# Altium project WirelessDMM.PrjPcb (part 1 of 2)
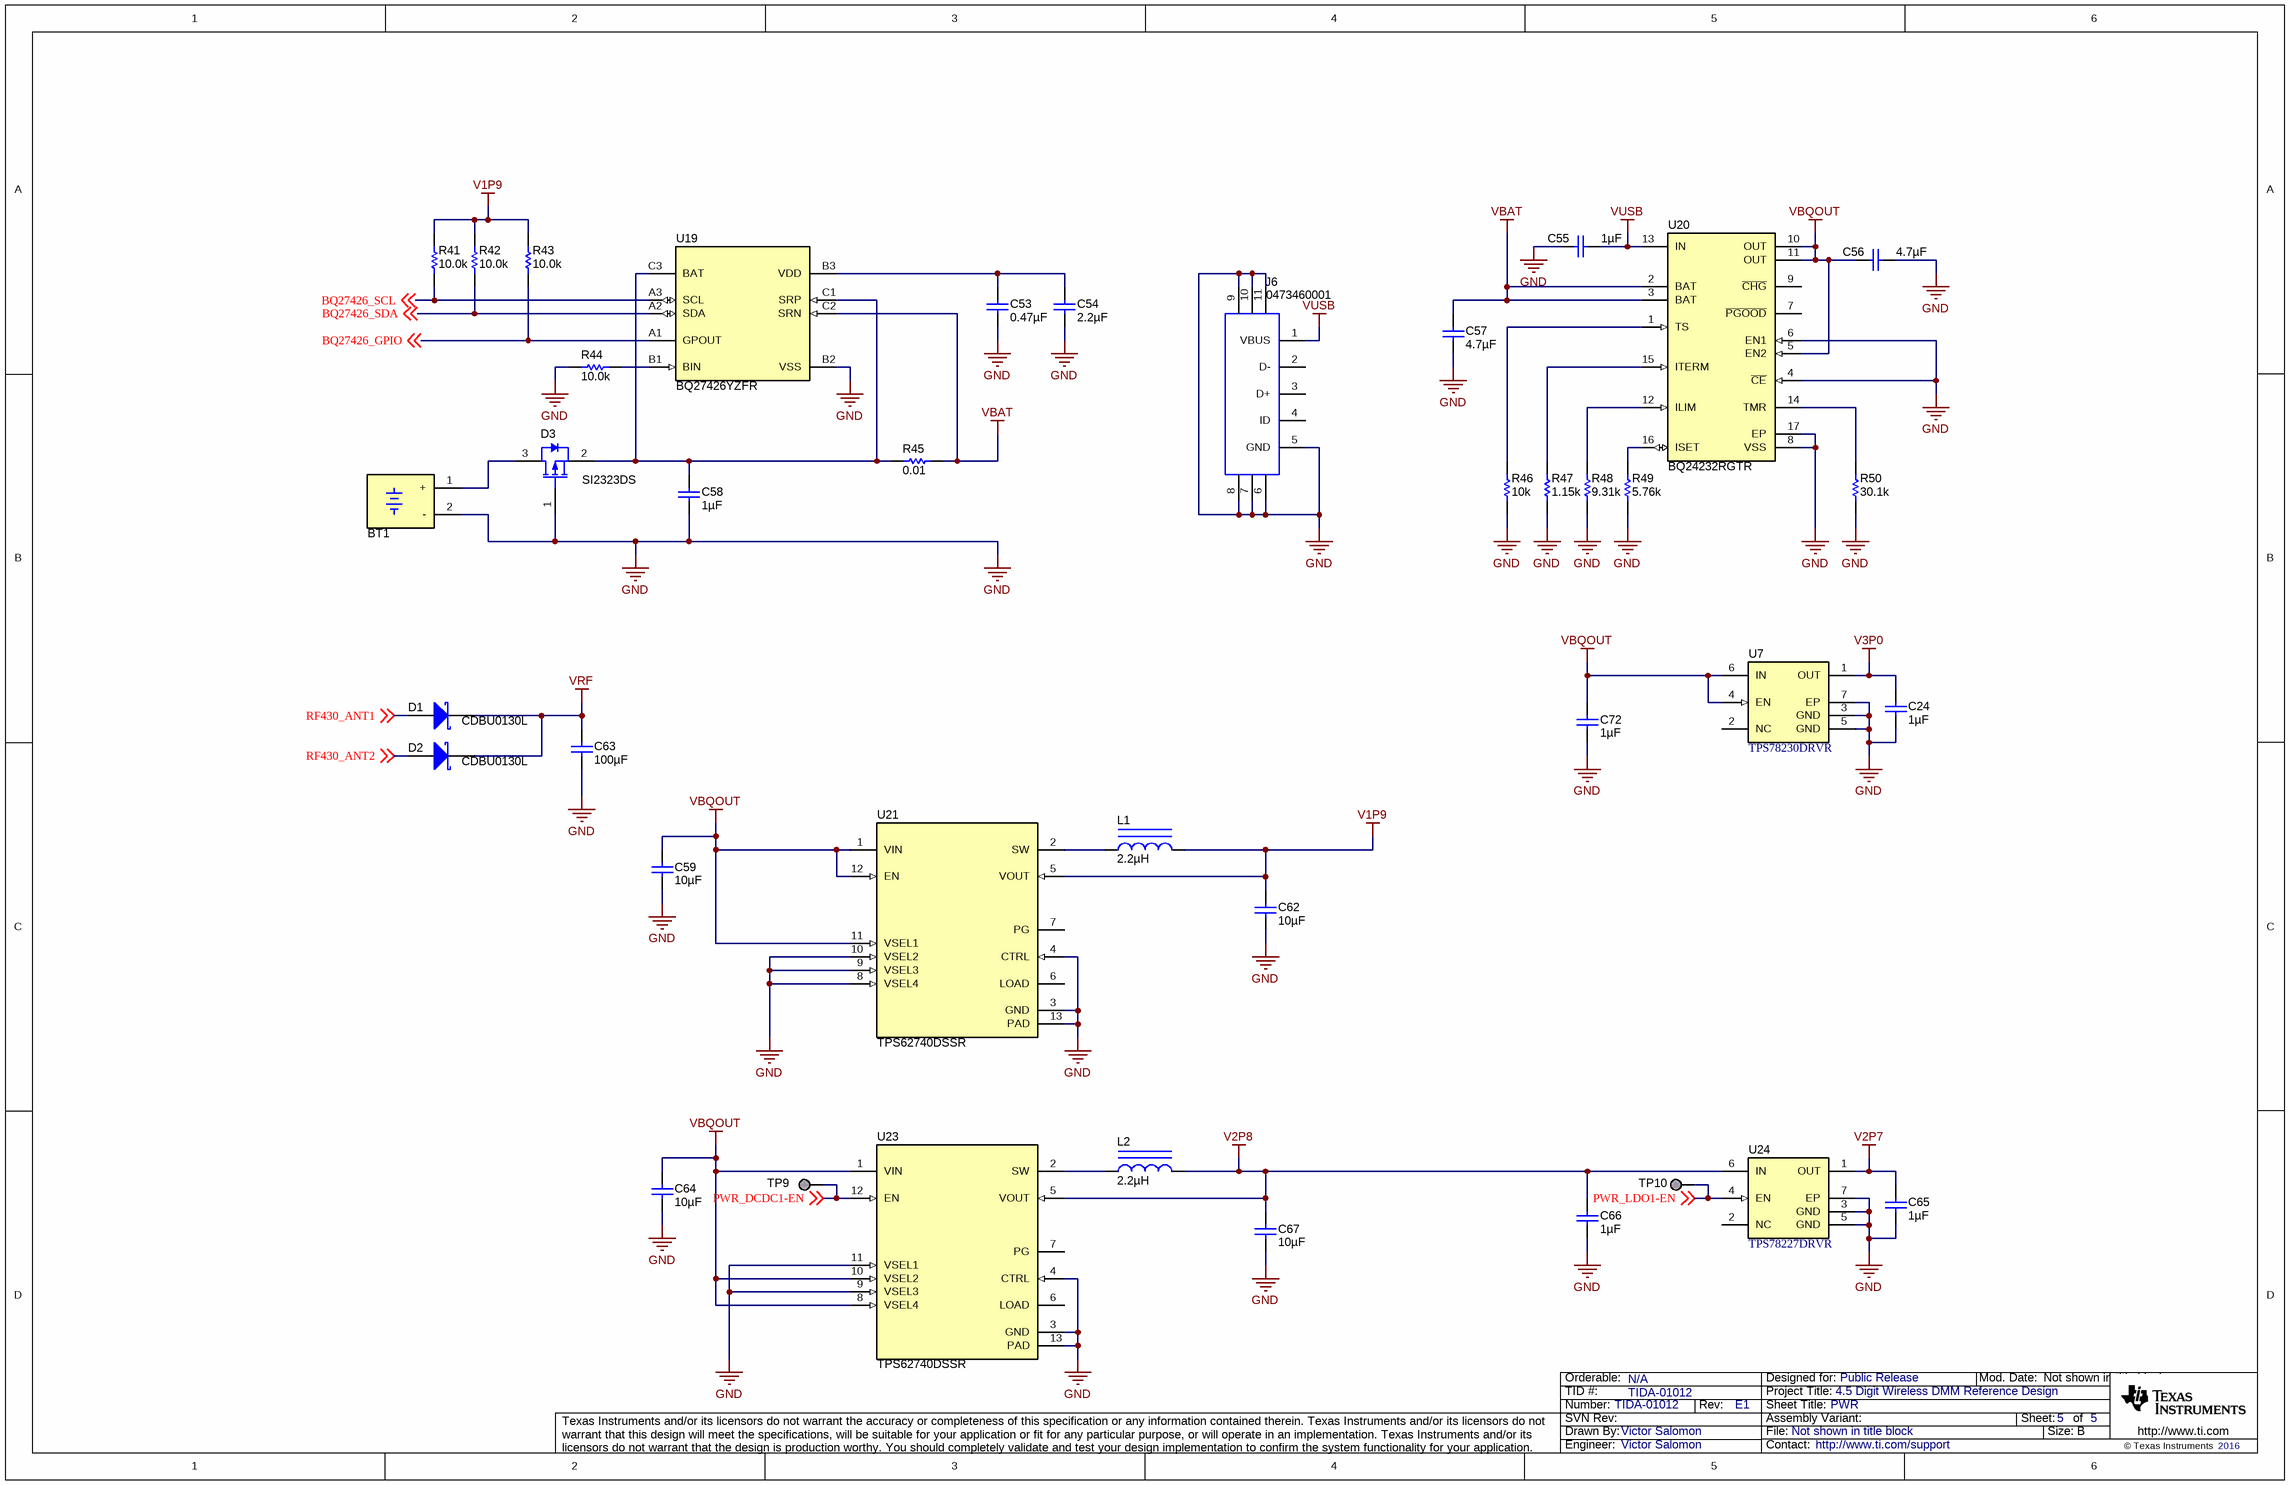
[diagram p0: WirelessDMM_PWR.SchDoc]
CopyrightYear: 2016; EVM_Orderable: N/A; PCB_Rev: E1; PRJ_Customer: Public Release; PRJ_Engineer: Victor Salomon; PRJ_Number: TIDA-01012; PRJ_Title: 4.5 Digit Wireless DMM Reference Design; SCH_Rev: E1; TechSupport: http://www.ti.com/support; TID: TIDA-01012
5 sheets, 199 parts. Net scope: flat (ports and power ports of the same name join across sheets).
Board file: WirelessDMM.PcbDoc
Sheets:
  WirelessDMM_PWR.SchDoc
  WirelessDMM_MCU.SchDoc
  WirelessDMM_AFE.SchDoc
  WirelessDMM_Hardware.SchDoc
  WirelessDMM_Block_Diagram.SchDoc

## Sheet WirelessDMM_PWR.SchDoc: PWR
size 431 x 279 mm; Date: Not shown in title block; ApprovedBy: Not shown in title block; CheckedBy: Not shown in title block; Author: Not shown in title block; CompanyName: Not shown in title block; DrawnBy: Victor Salomon; Engineer: Not shown in title block; Organization: Not shown in title block; Address1: Not shown in title block; Address2: Not shown in title block; Address3: Not shown in title block; Address4: Not shown in title block; DocumentNumber: 1; Revision: Use project parameter SCH_Rev; SheetNumber: 5; SheetTotal: 5; PageSetup: Record=PageOptions¦CenterHorizontal=True¦CenterVertical=True¦PrintScale=0.64¦XCorrection=1.00¦YCorrection=1.00¦PrintKind=0¦BorderSize=5000000¦LeftOffset=0¦BottomOffset=0¦Orientation=2¦PaperLength=1000¦PaperWidth=1000¦Scale=100¦PaperSource=15¦PrintQuality=600¦MediaType=1¦DitherType=10¦PrintScaleMode=1¦PaperKind=Letter

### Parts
BT1  1021  [Keystone_1021]  (value not drawn)
C24  ValueDisplayed: 1µF  [0402S]  (hidden comment: GRM155R61A105KE15D)
C53  ValueDisplayed: 0.47µF  [0201_033]  (hidden comment: GRM033R60J474KE90D)
C54  ValueDisplayed: 2.2µF  [0402S]  (hidden comment: GRM155R61C225KE11D)
C55  ValueDisplayed: 1µF  [0402S]  (hidden comment: GRM155R61A105KE15D)
C56  ValueDisplayed: 4.7µF  [0402S]  (hidden comment: C1005X5R1A475K050BC)
C57  ValueDisplayed: 4.7µF  [0402S]  (hidden comment: C1005X5R1A475K050BC)
C58  ValueDisplayed: 1µF  [0402S]  (hidden comment: GRM155R61A105KE15D)
C59  ValueDisplayed: 10µF  [0402S]  (hidden comment: CL05A106MP5NUNC)
C62  ValueDisplayed: 10µF  [0402S]  (hidden comment: CL05A106MP5NUNC)
C63  ValueDisplayed: 100µF  [1206_190L]  (hidden comment: C3216X5R1A107M160AC)
C64  ValueDisplayed: 10µF  [0402S]  (hidden comment: CL05A106MP5NUNC)
C65  ValueDisplayed: 1µF  [0402S]  (hidden comment: GRM155R61A105KE15D)
C66  ValueDisplayed: 1µF  [0402S]  (hidden comment: GRM155R61A105KE15D)
C67  ValueDisplayed: 10µF  [0402S]  (hidden comment: CL05A106MP5NUNC)
C72  ValueDisplayed: 1µF  [0402S]  (hidden comment: GRM155R61A105KE15D)
D1  CDBU0130L  [SOD-523F]
D2  CDBU0130L  [SOD-523F]
D3  SI2323DS  [SOT-23]
J6  0473460001  [CONN_47346-0001]
L1  ValueDisplayed: 2.2µH  [0805M]  (hidden comment: MLZ2012A2R2WT000)
L2  ValueDisplayed: 2.2µH  [0805M]  (hidden comment: MLZ2012A2R2WT000)
R41  ValueDisplayed: 10.0k  [0201M]  (hidden comment: CRCW020110K0FKED)
R42  ValueDisplayed: 10.0k  [0201M]  (hidden comment: CRCW020110K0FKED)
R43  ValueDisplayed: 10.0k  [0201M]  (hidden comment: CRCW020110K0FKED)
R44  ValueDisplayed: 10.0k  [0402S]  (hidden comment: ERJ-2RKF1002X)
R45  ValueDisplayed: 0.01  [0805_HV]  (hidden comment: WSL0805R0100FEA18)
R46  ValueDisplayed: 10k  [0402S]  (hidden comment: CRCW040210K0JNED)
R47  ValueDisplayed: 1.15k  [0402S]  (hidden comment: CRCW04021K15FKED)
R48  ValueDisplayed: 9.31k  [0402S]  (hidden comment: CRCW04029K31FKED)
R49  ValueDisplayed: 5.76k  [0402S]  (hidden comment: CRCW04025K76FKED)
R50  ValueDisplayed: 30.1k  [0402S]  (hidden comment: CRCW040230K1FKED)
TP9  TESTPOINT  [TP_SM_1MM]  (value not drawn)  (no BOM)
TP10  TESTPOINT  [TP_SM_1MM]  (value not drawn)  (no BOM)
U7  TPS78230DRVR  [DRV0006A]
U19  BQ27426YZFR  [YZF0009-C01]
U20  BQ24232RGTR  [RGT0016C]
U21  TPS62740DSSR  [DSS0012A]
U23  TPS62740DSSR  [DSS0012A]
U24  TPS78227DRVR  [DRV0006A]

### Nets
GND: BT1.2(-) C24.2 C53.2 C54.2 C55.1 C56.2 C57.2 C58.2 C59.2 C62.2 C63.2 C64.2 C65.2 C66.2 C67.2 C72.2 D3.1(G) J6.5(GND) J6.6 J6.7 J6.8 J6.9 J6.10 J6.11 R44.2 R46.1 R47.1 R48.1 R49.1 R50.1 U7.3(GND) U7.5(GND) U7.7(EP) U19.B2(VSS) U20.4(~{CE}) U20.6(EN1) U20.8(VSS) U20.17(EP) U21.3(GND) U21.4(CTRL) U21.8(VSEL4) U21.9(VSEL3) U21.10(VSEL2) U21.13(PAD) U23.3(GND) U23.4(CTRL) U23.9(VSEL3) U23.11(VSEL1) U23.13(PAD) U24.3(GND) U24.5(GND) U24.7(EP)
V1P9: C62.1 L1.2 R41.2 R42.2 R43.2 U21.5(VOUT)
V2P7: C65.1 U24.1(OUT)
V2P8: C66.1 C67.1 L2.2 U23.5(VOUT) U24.6(IN)
V3P0: C24.1 U7.1(OUT)
VBAT: C57.1 R45.2 U19.C2(SRN) U20.2(BAT) U20.3(BAT)
VBQOUT: C56.1 C59.1 C64.1 C72.1 U7.4(EN) U7.6(IN) U20.5(EN2) U20.10(OUT) U20.11(OUT) U21.1(VIN) U21.11(VSEL1) U21.12(EN) U23.1(VIN) U23.8(VSEL4) U23.10(VSEL2)
VRF: C63.1 D1.1(K) D2.1(K)
VUSB: C55.2 J6.1(VBUS) U20.13(IN)
BQ27426_GPIO: R43.1 U19.A1(GPOUT) ; off-sheet BQ27426_GPIO
BQ27426_SCL: R41.1 U19.A3(SCL) ; off-sheet BQ27426_SCL
BQ27426_SDA: R42.1 U19.A2(SDA) ; off-sheet BQ27426_SDA
PWR_DCDC1-EN: TP9.1 U23.12(EN) ; off-sheet PWR_DCDC1-EN
PWR_LDO1-EN: TP10.1 U24.4(EN) ; off-sheet PWR_LDO1-EN
RF430_ANT1: D1.2(A) ; off-sheet RF430_ANT1
RF430_ANT2: D2.2(A) ; off-sheet RF430_ANT2
NetBT1_1: BT1.1(+) D3.3(D)
NetC53_1: C53.1 C54.1 U19.B3(VDD)
NetC58_1: C58.1 D3.2(S) R45.1 U19.C1(SRP) U19.C3(BAT)
NetL1_1: L1.1 U21.2(SW)
NetL2_1: L2.1 U23.2(SW)
NetR44_1: R44.1 U19.B1(BIN)
NetR46_2: R46.2 U20.1(TS)
NetR47_2: R47.2 U20.15(ITERM)
NetR48_2: R48.2 U20.12(ILIM)
NetR49_2: R49.2 U20.16(ISET)
NetR50_2: R50.2 U20.14(TMR)

Not connected (* = marked no-connect by the designer): J6 2(D-) 3(D+) 4(ID); U7 2(NC); U20 7(~{PGOOD}) 9(~{CHG}); U21 6(LOAD) 7(PG); U23 6(LOAD) 7(PG); U24 2(NC)

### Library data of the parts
BT1 = 1021: HOLDER BATTERY AAA, TH; Manufacturer: Keystone; SymbolCreator: a0411947; CompType: Battery Holder
C24 C55 C58 C65 C66 C72 = GRM155R61A105KE15D: CAP, CERM, 1 µF, 10 V, +/- 10%, X5R, 0402; Manufacturer: MuRata; Polarized: N; CompType: Capacitor; Value: 1uF; U/M: EA; Cap_F: 0.000001; Tolerance_%: 10; Value1: Unknown; Value2: 10V; TaMin_C: -55; TaMax_C: 85; Cap_Case: 0402; AEC Category: Q200
C53 = GRM033R60J474KE90D: CAP, CERM, 0.47 µF, 6.3 V, +/- 10%, X5R, 0201; Manufacturer: MuRata; Polarized: N; CompType: Capacitor; Value: 0.47uF; U/M: EA; Cap_F: 0.00000047; Tolerance_%: 10; Value1: Unknown; VDC_V: 6.3; Value2: 6.3V; TaMin_C: -55; TaMax_C: 85; Cap_Case: 0201; AEC Category: Q200
C54 = GRM155R61C225KE11D: CAP, CERM, 2.2 µF, 16 V, +/- 10%, X5R, 0402; Manufacturer: MuRata; Polarized: N; CompType: Capacitor; Value: 2.2uF; U/M: EA; Cap_F: 0.0000022; Tolerance_%: 10; Value1: Unknown; VDC_V: 16; Value2: 16V; TaMin_C: -55; TaMax_C: 85; Cap_Case: 0402; AEC Category: Q200
C56 C57 = C1005X5R1A475K050BC: CAP, CERM, 4.7 µF, 10 V, +/- 10%, X5R, 0402; Manufacturer: TDK; Polarized: N; CompType: Capacitor; Value: 4.7uF; U/M: EA; Cap_F: 0.0000047; Tolerance_%: 10; Value1: Unknown; Value2: 10V; TaMin_C: -55; TaMax_C: 85; Cap_Case: 0402; AEC Category: Q200
C59 C62 C64 C67 = CL05A106MP5NUNC: CAP, CERM, 10 µF, 10 V, +/- 20%, X5R, 0402; Manufacturer: Samsung Electro-Mechanics; Polarized: N; CompType: Capacitor; Value: 10uF; U/M: EA; Cap_F: 0.00001; Tolerance_%: 20; Value1: Unknown; VDC_V: 10; Value2: 10V; TaMin_C: -55; TaMax_C: 85; Cap_Case: 0402; AEC Category: Q200
C63 = C3216X5R1A107M160AC: CAP, CERM, 100 µF, 10 V, +/- 20%, X5R, 1206_190; Manufacturer: TDK; Polarized: N; CompType: Capacitor; Value: 100uF; U/M: EA; Cap_F: 0.0001; Tolerance_%: 20; Value1: Unknown; VDC_V: 10; Value2: 10V; TaMin_C: -55; TaMax_C: 85; Cap_Case: 1206; AEC Category: Q200
D1 D2 = CDBU0130L: Diode, Schottky, 35 V, 0.1 A, SOD-523F; Manufacturer: Comchip Technology; U/M: EA; Value: 35V; Value1: 0.1A; Io_A: 0.1; Vr_V: 35; TJmax_C: 125; AEC Category: Q101
D3 = SI2323DS: MOSFET, P-CH, -20 V, -3.7 A, SOT-23; Manufacturer: Vishay-Siliconix; Alternate Manufacturer: None; U/M: EA; ChType: P; Value: -20V; Value1: 0.031 ohm; Rdson45_ohm: 0.031; Value2: 12.5 nC; QgTyp_nC: 12.5; Vgs_V: -8; AEC Category: Q101
J6 = 0473460001: Connector, Receptacle, Micro-USB Type B, R/A, Bottom Mount SMT; Manufacturer: Molex; SymbolCreator: a0411947
L1 L2 = MLZ2012A2R2WT000: Inductor, Multilayer, Ferrite, 2.2 µH, 0.21 A, 0.15 ohm, SMD; Manufacturer: TDK; Value: 2.2uH; Ind_H: 2.2E-6; Imax_A: 0.21; Irms: 0.65A @ 20C rise; Isat: 0.21A @ 50% inductance drop; DCR_ohm: 0.15; Value2: 0.21A; AEC Category: Q200; AEC Qualified: N
R41-R43 = CRCW020110K0FKED: RES, 10.0 k, 1%, 0.05 W, 0201; Manufacturer: Vishay-Dale; CompType: Resistor; Value: 10.0k; Res_ohm: 10000; Value_Code: 10k0; Tolerance_%: 1; Power_W: 0.05; Value2: 0.05W; VDC_V: 30; TempCo: 100 ppm/C; EIA_Code: E96; U/M: EA; AEC Category: Q200; AEC Qualified: N
R44 = ERJ-2RKF1002X: RES, 10.0 k, 1%, 0.1 W, 0402; Manufacturer: Panasonic; CompType: Resistor; Value: 10.0k; Res_ohm: 10000; Value_Code: 10k0; Tolerance_%: 1; Power_W: 0.1; Value2: 0.1W; VDC_V: 50; TempCo: 100 ppm/C; EIA_Code: E96; U/M: EA; AEC Category: Q200
R45 = WSL0805R0100FEA18: RES, 0.01, 1%, 0.25 W, 0805; Manufacturer: Vishay-Dale; CompType: Resistor; Value: 0.01; Value_Code: R010; Tolerance_%: 1; Power_W: 0.25; Value2: 0.25W; TempCo: 75 ppm/C; EIA_Code: E96; U/M: EA; AEC Category: Q200
R46 = CRCW040210K0JNED: RES, 10 k, 5%, 0.063 W, 0402; Manufacturer: Vishay-Dale; CompType: Resistor; Value: 10k; Res_ohm: 10000; Value_Code: 10k0; Tolerance_%: 5; Power_W: 0.063; Value2: 0.063W; VDC_V: 50; TempCo: 200 ppm/C; EIA_Code: E24; U/M: EA; AEC Category: Q200
R47 = CRCW04021K15FKED: RES, 1.15 k, 1%, 0.063 W, 0402; Manufacturer: Vishay-Dale; CompType: Resistor; Value: 1.15k; Res_ohm: 1150; Value_Code: 1k15; Tolerance_%: 1; Power_W: 0.063; Value2: 0.063W; VDC_V: 50; TempCo: 100 ppm/C; EIA_Code: E96; U/M: EA; AEC Category: Q200
R48 = CRCW04029K31FKED: RES, 9.31 k, 1%, 0.063 W, 0402; Manufacturer: Vishay-Dale; CompType: Resistor; Value: 9.31k; Res_ohm: 9310; Value_Code: 9k31; Tolerance_%: 1; Power_W: 0.063; Value2: 0.063W; VDC_V: 50; TempCo: 100 ppm/C; EIA_Code: E96; U/M: EA; AEC Category: Q200; SizeArea_mm2: 0.5; SizeZ_mm: 0.6
R49 = CRCW04025K76FKED: RES, 5.76 k, 1%, 0.063 W, 0402; Manufacturer: Vishay-Dale; CompType: Resistor; Value: 5.76k; Res_ohm: 5760; Value_Code: 5k76; Tolerance_%: 1; Power_W: 0.063; Value2: 0.063W; VDC_V: 50; TempCo: 100 ppm/C; EIA_Code: E96; U/M: EA; AEC Category: Q200
R50 = CRCW040230K1FKED: RES, 30.1 k, 1%, 0.063 W, 0402; Manufacturer: Vishay-Dale; CompType: Resistor; Value: 30.1k; Res_ohm: 30100; Value_Code: 30k1; Tolerance_%: 1; Power_W: 0.063; Value2: 0.063W; VDC_V: 50; TempCo: 100 ppm/C; EIA_Code: E96; U/M: EA; AEC Category: Q200
TP9 TP10 = TP_SM_1MM: 1mm Test Point, SMT; Manufacturer: Any
U7 = TPS78230DRVR: Single Output LDO, 150 mA, Fixed 3 V Output, 2.2 to 5.5 V Input, with 0.5 uA Quiescent Current, 6-pin SON (DRV), -40 to 125 degC, Green (RoHS & no Sb/Br); Manufacturer: Texas Instruments; Alternate PartNumber: Equivalent; Accuracy(%): 3; Dynamic Voltage Scaling: TRUE; Iout(Max)(A): 0.15; Iq(Typ)(mA): 0.0005; Rating: Catalog; SubFamily: Single Channel LDO; Vdo(Typ)(mV): 130; Vin(Max)(V): 5.5; Vin(Min)(V): 2.2
U19 = BQ27426YZFR: System-Side Impedance Track Fuel Gauge, YZF0009-C01; Alternate PartNumber: BQ27426YZFT; Manufacturer: Texas Instruments; SymbolCreator: Altium; CompType: IC; U/M: EA
U20 = BQ24232RGTR: USB Friendly 0.5 A Li+ Charger with Dynamic Power Management, 10.5 V OVP, 4.3 V, -40 to 85 degC, 16-pin QFN (RGT), Green (RoHS & no Sb/Br); Manufacturer: Texas Instruments; Alternate PartNumber: Equivalent; Lead Acid: N; SubFamily: Battery Charge Management; Vin(Min)(V): 4.3
U21 U23 = TPS62740DSSR: 360nA IQ Step Down Converter for Low Power Applications, DSS0012A; Alternate PartNumber: TPS62740DSST; Manufacturer: Texas Instruments; SymbolCreator: Altium; CompType: IC; U/M: EA
U24 = TPS78227DRVR: Single Output LDO, 150 mA, Fixed 2.7 V Output, 2.2 to 5.5 V Input, with 0.5 uA Quiescent Current, 6-pin SON (DRV), -40 to 85 degC, Green (RoHS & no Sb/Br); Manufacturer: Texas Instruments; Alternate PartNumber: Equivalent; Accuracy(%): 3; Dynamic Voltage Scaling: TRUE; Fixed Output Options(V): 2.7; Iout(Max)(A): 0.15; Iq(Typ)(mA): 0.0005; Rating: Catalog; SubFamily: Single Channel LDO; Vdo(Typ)(mV): 130; Vin(Max)(V): 5.5; Vin(Min)(V): 2.2

## Sheet WirelessDMM_MCU.SchDoc: MCU
size 431 x 279 mm; Date: Not shown in title block; ApprovedBy: Not shown in title block; CheckedBy: Not shown in title block; Author: Not shown in title block; CompanyName: Not shown in title block; DrawnBy: Victor Salomon; Engineer: Not shown in title block; Organization: Not shown in title block; Address1: Not shown in title block; Address2: Not shown in title block; Address3: Not shown in title block; Address4: Not shown in title block; DocumentNumber: 2; Revision: Use project parameter SCH_Rev; SheetNumber: 2; SheetTotal: 5; PageSetup: Record=PageOptions¦CenterHorizontal=True¦CenterVertical=True¦PrintScale=1.00¦XCorrection=1.00¦YCorrection=1.00¦PrintKind=0¦BorderSize=5000000¦LeftOffset=0¦BottomOffset=0¦Orientation=2¦PaperLength=1000¦PaperWidth=1000¦Scale=100¦PaperSource=15¦PrintQuality=600¦MediaType=1¦DitherType=10¦PaperKind=Letter¦PrintScaleMode=1
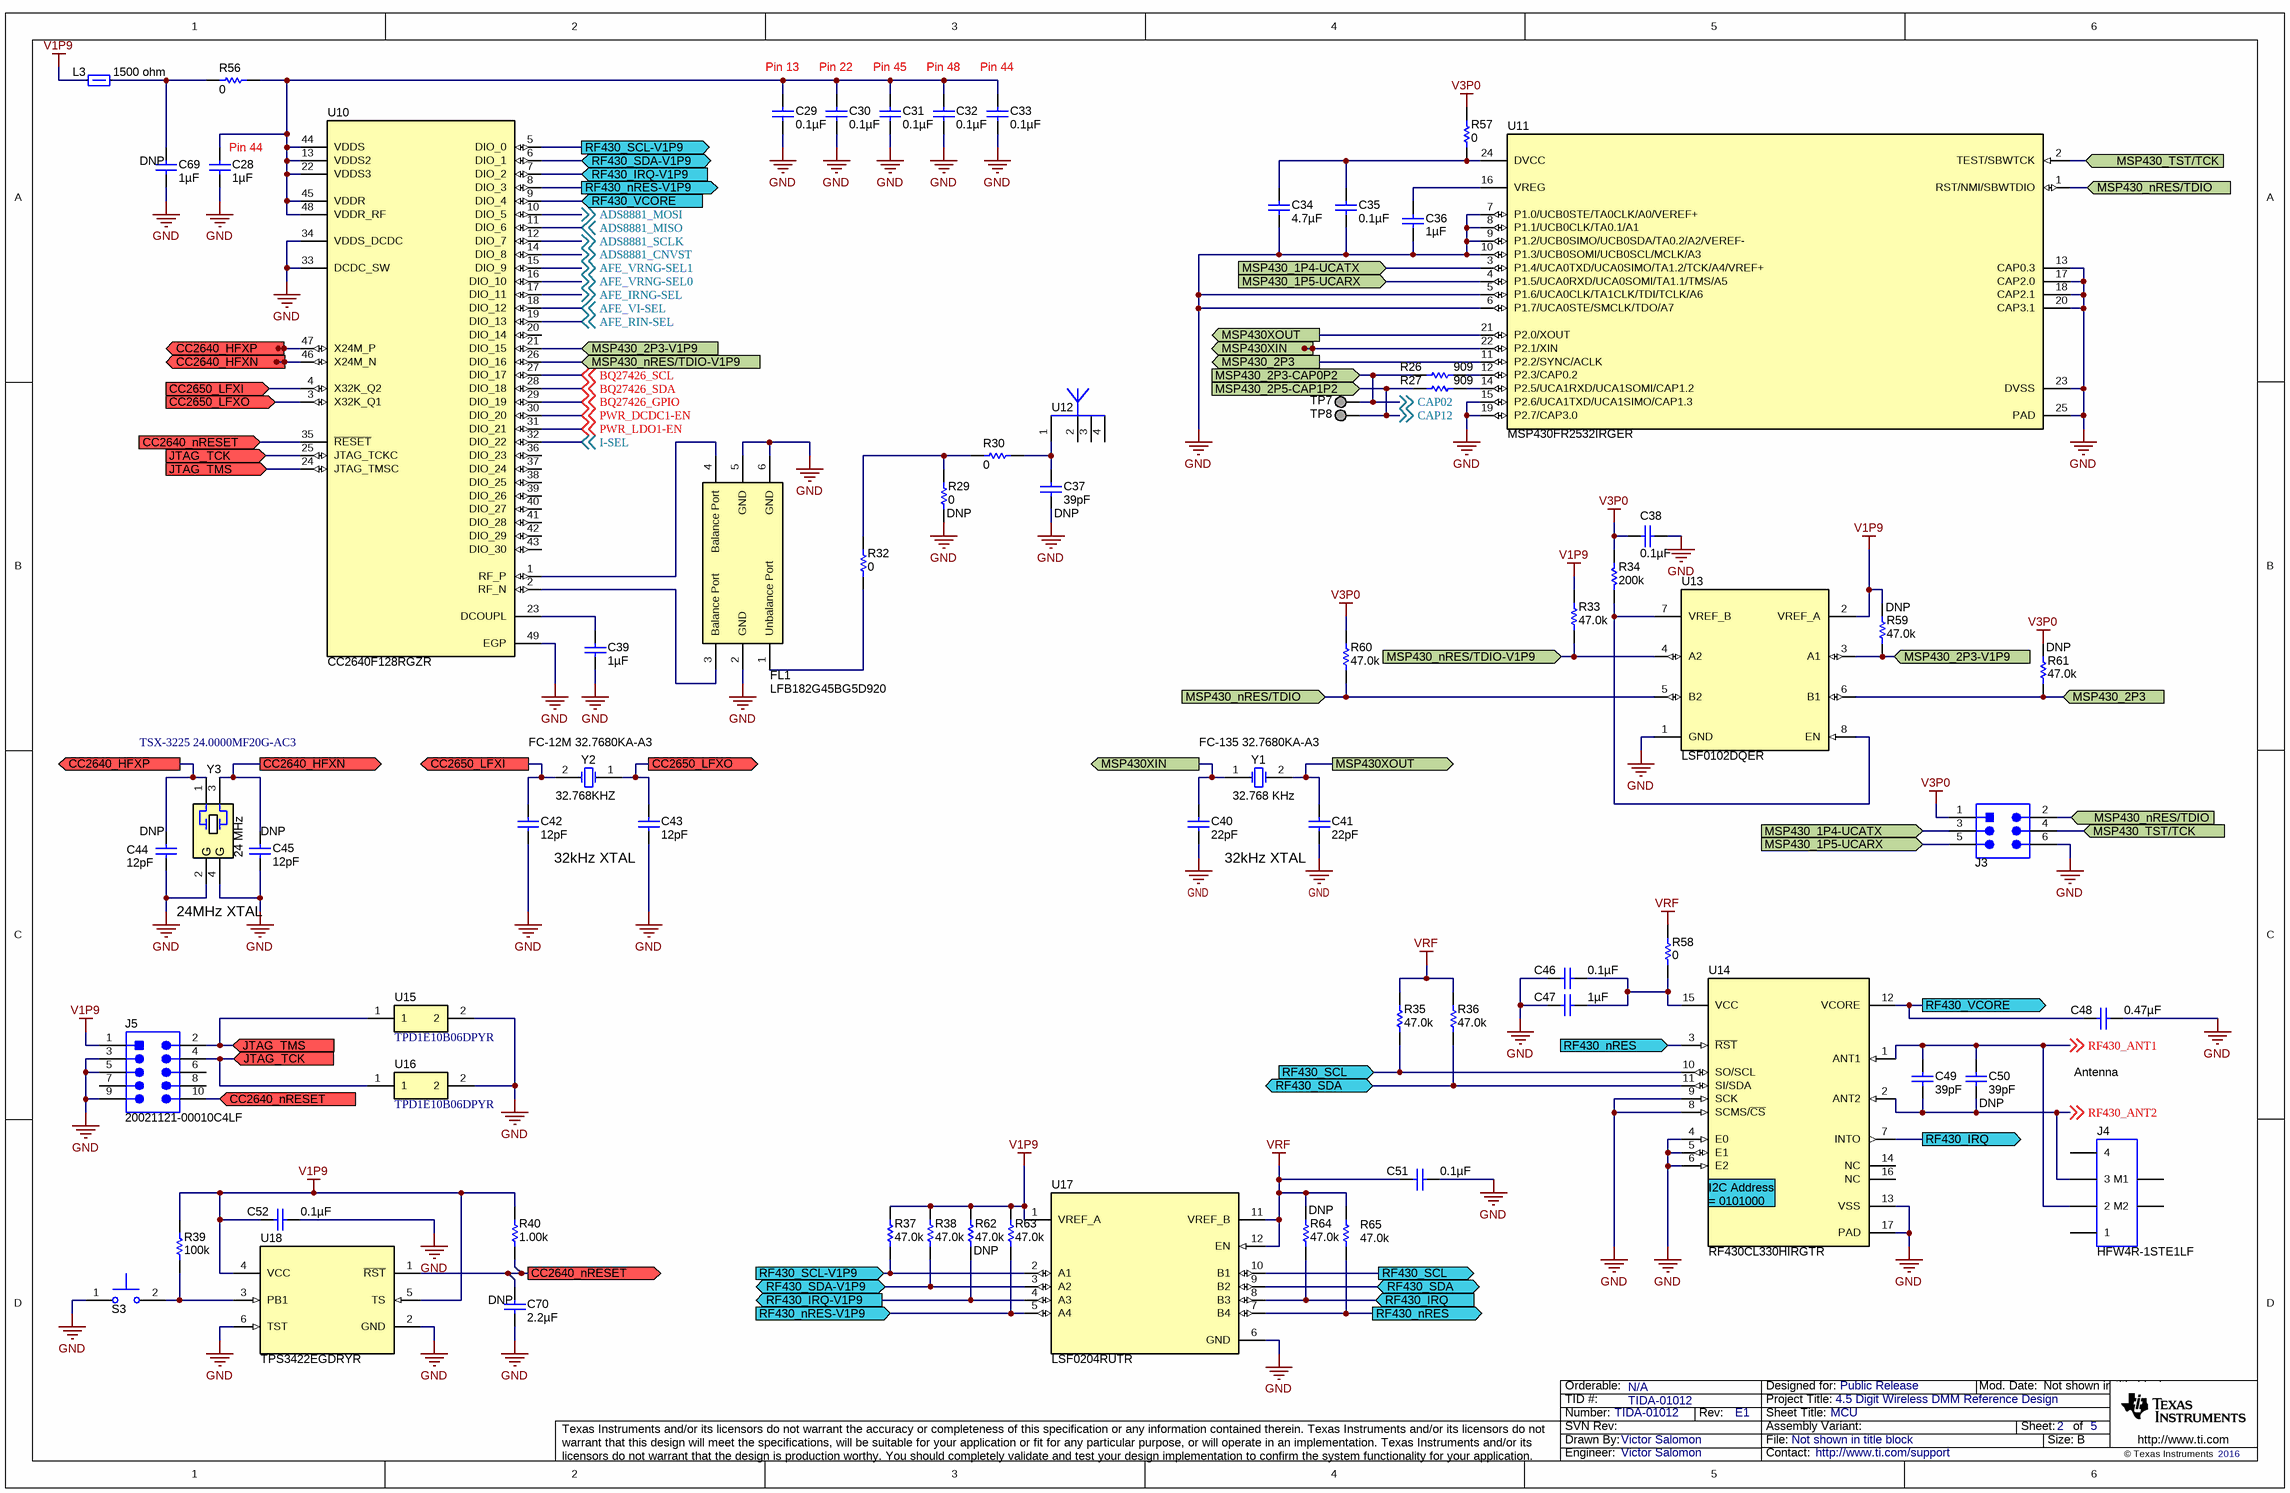
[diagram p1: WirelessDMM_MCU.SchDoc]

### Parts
C28  ValueDisplayed: 1µF  [0402S]  (hidden comment: GRM155R61A105KE15D)
C29  ValueDisplayed: 0.1µF  [0201]  (hidden comment: CL03A104KP3NNNC)
C30  ValueDisplayed: 0.1µF  [0201]  (hidden comment: CL03A104KP3NNNC)
C31  ValueDisplayed: 0.1µF  [0201]  (hidden comment: CL03A104KP3NNNC)
C32  ValueDisplayed: 0.1µF  [0201]  (hidden comment: CL03A104KP3NNNC)
C33  ValueDisplayed: 0.1µF  [0201]  (hidden comment: CL03A104KP3NNNC)
C34  ValueDisplayed: 4.7µF  [0402S]  (hidden comment: C1005X5R1A475K050BC)
C35  ValueDisplayed: 0.1µF  [0201]  (hidden comment: CL03A104KP3NNNC)
C36  ValueDisplayed: 1µF  [0402S]  (hidden comment: GRM155R61A105KE15D)
C37  ValueDisplayed: 39pF  [0402S]  (hidden comment: GRM1555C1H390JA01D)
C38  ValueDisplayed: 0.1µF  [0201]  (hidden comment: CL03A104KP3NNNC)
C39  ValueDisplayed: 1µF  [0402S]  (hidden comment: C1005X5R0J105M050BB)
C40  ValueDisplayed: 22pF  [0201_033]  (hidden comment: GCM0335C1E220JD03D)
C41  ValueDisplayed: 22pF  [0201_033]  (hidden comment: GCM0335C1E220JD03D)
C42  ValueDisplayed: 12pF  [0201]  (hidden comment: GRM0335C1H120JA01D)
C43  ValueDisplayed: 12pF  [0201]  (hidden comment: GRM0335C1H120JA01D)
C44  ValueDisplayed: 12pF  [0201]  (hidden comment: GRM0335C1H120JA01D)
C45  ValueDisplayed: 12pF  [0201]  (hidden comment: GRM0335C1H120JA01D)
C46  ValueDisplayed: 0.1µF  [0201]  (hidden comment: CL03A104KP3NNNC)
C47  ValueDisplayed: 1µF  [0402S]  (hidden comment: GRM155R61A105KE15D)
C48  ValueDisplayed: 0.47µF  [0201_033]  (hidden comment: GRM033R60J474KE90D)
C49  ValueDisplayed: 39pF  [0402S]  (hidden comment: GRM1555C1H390JA01D)
C50  ValueDisplayed: 39pF  [0402S]  (hidden comment: GRM1555C1H390JA01D)
C51  ValueDisplayed: 0.1µF  [0201]  (hidden comment: CL03A104KP3NNNC)
C52  ValueDisplayed: 0.1µF  [0201]  (hidden comment: CL03A104KP3NNNC)
C69  ValueDisplayed: 1µF  [0402S]  (hidden comment: GRM155R61A105KE15D)
C70  ValueDisplayed: 2.2µF  [0402S]  (hidden comment: CL05A225KQ5NNNC)
FL1  LFB182G45BG5D920  [Murata_LFB182G45BG5D920]
J3  20021121-00006C4LF  [FCI_20021121-00006x4]  (value not drawn)
J4  HFW4R-1STE1LF  [HFW4R-1STE1LF]
J5  20021121-00010C4LF  [FCI_20021121-00010xxLF]
L3  value 1500 ohm  [0603S]  (hidden comment: BLM18HE152SN1D)
R26  ValueDisplayed: 909  [0201M]  (hidden comment: CRCW0201909RFKED)
R27  ValueDisplayed: 909  [0201M]  (hidden comment: CRCW0201909RFKED)
R29  ValueDisplayed: 0  [0402S]  (hidden comment: MCR01MZPJ000)
R30  ValueDisplayed: 0  [0402S]  (hidden comment: MCR01MZPJ000)
R32  ValueDisplayed: 0  [0402S]  (hidden comment: MCR01MZPJ000)
R33  ValueDisplayed: 47.0k  [0201M]  (hidden comment: RK73H1HTTC4702F)
R34  ValueDisplayed: 200k  [0402S]  (hidden comment: CRCW0402200KFKED)
R35  ValueDisplayed: 47.0k  [0201M]  (hidden comment: RK73H1HTTC4702F)
R36  ValueDisplayed: 47.0k  [0201M]  (hidden comment: RK73H1HTTC4702F)
R37  ValueDisplayed: 47.0k  [0201M]  (hidden comment: RK73H1HTTC4702F)
R38  ValueDisplayed: 47.0k  [0201M]  (hidden comment: RK73H1HTTC4702F)
R39  ValueDisplayed: 100k  [0201M]  (hidden comment: CRCW0201100KFKED)
R40  ValueDisplayed: 1.00k  [0201M]  (hidden comment: CRCW02011K00FKED)
R56  ValueDisplayed: 0  [0402S]  (hidden comment: MCR01MZPJ000)
R57  ValueDisplayed: 0  [0402S]  (hidden comment: MCR01MZPJ000)
R58  ValueDisplayed: 0  [0402S]  (hidden comment: MCR01MZPJ000)
R59  ValueDisplayed: 47.0k  [0201M]  (hidden comment: RK73H1HTTC4702F)
R60  ValueDisplayed: 47.0k  [0201M]  (hidden comment: RK73H1HTTC4702F)
R61  ValueDisplayed: 47.0k  [0201M]  (hidden comment: RK73H1HTTC4702F)
R62  ValueDisplayed: 47.0k  [0201M]  (hidden comment: RK73H1HTTC4702F)
R63  ValueDisplayed: 47.0k  [0201M]  (hidden comment: RK73H1HTTC4702F)
R64  ValueDisplayed: 47.0k  [0201M]  (hidden comment: RK73H1HTTC4702F)
R65  47.0k  [0201M]
S3  B3U-1000P  [SW_B3U-1000P]  (value not drawn)
TP7  TESTPOINT  [TP_H045P075]  (value not drawn)  (no BOM)
TP8  TESTPOINT  [TP_H045P075]  (value not drawn)  (no BOM)
U10  CC2640F128RGZR  [RGZ0048A]
U11  MSP430FR2532IRGER  [RGE0024G]
U12  479480001  [Molex_0479480001]  (value not drawn)
U13  LSF0102DQER  [DQE0008A]
U14  RF430CL330HIRGTR  [RGT0016C]
U15  TPD1E10B06DPYR  [DPY0002A]
U16  TPD1E10B06DPYR  [DPY0002A]
U17  LSF0204RUTR  [RUT0012A]
U18  TPS3422EGDRYR  [DRY0006A]
Y1  FC-135 32.7680KA-A3  Frequency: 32.768 KHz  [Epson_FC-135]
Y2  FC-12M 32.7680KA-A3  Frequency: 32.768KHZ  [Epson_FC-12M]
Y3  TSX-3225 24.0000MF20G-AC3  Frequency: 24 MHz  [EPSON_TSX-3225]

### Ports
CC2640_HFXN (in), CC2640_HFXN (out), CC2640_HFXP (in), CC2640_HFXP (out), CC2640_nRESET, CC2640_nRESET (in), CC2640_nRESET (out), CC2650_LFXI (in), CC2650_LFXI (out), CC2650_LFXO (in), CC2650_LFXO (out), JTAG_TCK (in), JTAG_TMS (in), MSP430_1P4-UCATX (in), MSP430_1P5-UCARX (in), MSP430_2P3 (in), MSP430_2P3 (out), MSP430_2P3-CAP0P2 (in), MSP430_2P3-V1P9 (in), MSP430_2P5-CAP1P2 (in), MSP430_nRES/TDIO (in), MSP430_nRES/TDIO-V1P9 (in), MSP430_TST/TCK (in), MSP430XIN, MSP430XIN (out), MSP430XOUT, MSP430XOUT (out), RF430_IRQ (in), RF430_IRQ (out), RF430_IRQ-V1P9 (in), RF430_IRQ-V1P9 (out), RF430_nRES (in), RF430_nRES (out), RF430_nRES-V1P9 (in), RF430_nRES-V1P9 (out), RF430_SCL (in), RF430_SCL (out), RF430_SCL-V1P9 (in), RF430_SCL-V1P9 (out), RF430_SDA (bidir), RF430_SDA-V1P9 (bidir), RF430_VCORE (in), RF430_VCORE (out)

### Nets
GND: C28.2 C29.2 C30.2 C31.2 C32.2 C33.2 C34.2 C35.2 C36.2 C37.2 C38.1 C39.2 C40.2 C41.2 C42.1 C43.2 C44.2 C45.2 C46.2 C47.2 C48.2 C51.1 C52.2 C69.2 C70.2 FL1.2(GND) FL1.5(GND) FL1.6(GND) J3.6 J5.3 J5.5 J5.9 R29.1 S3.1 U10.33(DCDC_SW) U10.34(VDDS_DCDC) U10.49(EGP) U11.5(P1.6/UCA0CLK/TA1CLK/TDI/TCLK/A6) U11.6(P1.7/UCA0STE/SMCLK/TDO/A7) U11.7(P1.0/UCB0STE/TA0CLK/A0/VEREF+) U11.8(P1.1/UCB0CLK/TA0.1/A1) U11.9(P1.2/UCB0SIMO/UCB0SDA/TA0.2/A2/VEREF-) U11.10(P1.3/UCB0SOMI/UCB0SCL/MCLK/A3) U11.13(CAP0.3) U11.15(P2.6/UCA1TXD/UCA1SIMO/CAP1.3) U11.17(CAP2.0) U11.18(CAP2.1) U11.19(P2.7/CAP3.0) U11.20(CAP3.1) U11.23(DVSS) U11.25(PAD) U13.1(GND) U14.4(E0) U14.5(E1) U14.6(E2) U14.8(SCMS/~{CS}) U14.9(SCK) U14.13(VSS) U14.17(PAD) U15.2 U16.2 U17.6(GND) U18.2(GND) U18.6(TST) Y3.2(GND) Y3.4(GND)
V1P9: C52.1 J5.1 L3.1 R33.2 R37.1 R38.1 R39.2 R40.2 R59.2 R62.2 R63.2 U13.2(VREF_A) U17.1(VREF_A) U18.4(VCC) U18.5(TS)
V3P0: C38.2 J3.1 R34.1 R57.2 R60.1 R61.2
VRF: C51.2 R35.2 R36.2 R58.2 R64.2 R65.2 U17.11(VREF_B) U17.12(EN)
ADS8881_CNVST: U10.14(DIO_8) ; off-sheet ADS8881_CNVST
ADS8881_MISO: U10.11(DIO_6) ; off-sheet ADS8881_MISO
ADS8881_MOSI: U10.10(DIO_5) ; off-sheet ADS8881_MOSI
ADS8881_SCLK: U10.12(DIO_7) ; off-sheet ADS8881_SCLK
AFE_IRNG-SEL: U10.17(DIO_11) ; off-sheet AFE_IRNG-SEL
AFE_RIN-SEL: U10.19(DIO_13) ; off-sheet AFE_RIN-SEL
AFE_VI-SEL: U10.18(DIO_12) ; off-sheet AFE_VI-SEL
AFE_VRNG-SEL0: U10.16(DIO_10) ; off-sheet AFE_VRNG-SEL0
AFE_VRNG-SEL1: U10.15(DIO_9) ; off-sheet AFE_VRNG-SEL1
BQ27426_GPIO: U10.29(DIO_19) ; off-sheet BQ27426_GPIO
BQ27426_SCL: U10.27(DIO_17) ; off-sheet BQ27426_SCL
BQ27426_SDA: U10.28(DIO_18) ; off-sheet BQ27426_SDA
CAP02: R26.1 TP7.1 ; off-sheet CAP02, port MSP430_2P3-CAP0P2
CAP12: R27.1 TP8.1 ; off-sheet CAP12, port MSP430_2P5-CAP1P2
CC2640_HFXN: C45.1 U10.46(X24M_N) Y3.3 ; port CC2640_HFXN
CC2640_HFXP: C44.1 U10.47(X24M_P) Y3.1 ; port CC2640_HFXP
CC2640_nRESET: C70.1 J5.10 R40.1 U10.35(~{RESET}) U18.1(~{RST}) ; port CC2640_nRESET
CC2650_LFXI: C42.2 U10.4(X32K_Q2) Y2.2(OSC2) ; port CC2650_LFXI
CC2650_LFXO: C43.1 U10.3(X32K_Q1) Y2.1(OSC1) ; port CC2650_LFXO
I-SEL: U10.32(DIO_22) ; off-sheet I-SEL
JTAG_TCK: J5.4 U10.25(JTAG_TCKC) U16.1 ; port JTAG_TCK
JTAG_TMS: J5.2 U10.24(JTAG_TMSC) U15.1 ; port JTAG_TMS
MSP430_1P4-UCATX: J3.3 U11.3(P1.4/UCA0TXD/UCA0SIMO/TA1.2/TCK/A4/VREF+) ; port MSP430_1P4-UCATX
MSP430_1P5-UCARX: J3.5 U11.4(P1.5/UCA0RXD/UCA0SOMI/TA1.1/TMS/A5) ; port MSP430_1P5-UCARX
MSP430_2P3: R61.1 U11.11(P2.2/SYNC/ACLK) U13.6(B1) ; port MSP430_2P3
MSP430_2P3-V1P9: R59.1 U10.21(DIO_15) U13.3(A1) ; port MSP430_2P3-V1P9
MSP430_nRES/TDIO: J3.2 R60.2 U11.1(RST/NMI/SBWTDIO) U13.5(B2) ; port MSP430_nRES/TDIO
MSP430_nRES/TDIO-V1P9: R33.1 U10.26(DIO_16) U13.4(A2) ; port MSP430_nRES/TDIO-V1P9
MSP430_TST/TCK: J3.4 U11.2(TEST/SBWTCK) ; port MSP430_TST/TCK
MSP430XIN: C40.1 U11.22(P2.1/XIN) Y1.1(OSC1) ; port MSP430XIN
MSP430XOUT: C41.1 U11.21(P2.0/XOUT) Y1.2(OSC2) ; port MSP430XOUT
PWR_DCDC1-EN: U10.30(DIO_20) ; off-sheet PWR_DCDC1-EN
PWR_LDO1-EN: U10.31(DIO_21) ; off-sheet PWR_LDO1-EN
RF430_ANT1: C49.1 C50.1 J4.2 U14.1(ANT1) ; off-sheet RF430_ANT1
RF430_ANT2: C49.2 C50.2 J4.3 U14.2(ANT2) ; off-sheet RF430_ANT2
RF430_IRQ: R64.1 U14.7(INTO) U17.8(B3) ; port RF430_IRQ
RF430_IRQ-V1P9: R62.1 U10.7(DIO_2) U17.4(A3) ; port RF430_IRQ-V1P9
RF430_nRES: R65.1 U14.3(~{RST}) U17.7(B4) ; port RF430_nRES
RF430_nRES-V1P9: R63.1 U10.8(DIO_3) U17.5(A4) ; port RF430_nRES-V1P9
RF430_SCL: R35.1 U14.10(SO/SCL) U17.10(B1) ; port RF430_SCL
RF430_SCL-V1P9: R37.2 U10.5(DIO_0) U17.2(A1) ; port RF430_SCL-V1P9
RF430_SDA: R36.1 U14.11(SI/SDA) U17.9(B2) ; port RF430_SDA
RF430_SDA-V1P9: R38.2 U10.6(DIO_1) U17.3(A2) ; port RF430_SDA-V1P9
RF430_VCORE: C48.1 U10.9(DIO_4) U14.12(VCORE) ; port RF430_VCORE
NetC28_1: C28.1 C29.1 C30.1 C31.1 C32.1 C33.1 R56.1 U10.13(VDDS2) U10.22(VDDS3) U10.44(VDDS) U10.45(VDDR) U10.48(VDDR_RF)
NetC34_1: C34.1 C35.1 R57.1 U11.24(DVCC)
NetC36_1: C36.1 U11.16(VREG)
NetC37_1: C37.1 R30.1 U12.1(Feeding_Point)
NetC39_1: C39.1 U10.23(DCOUPL)
NetC46_1: C46.1 C47.1 R58.1 U14.15(VCC)
NetC69_1: C69.1 L3.2 R56.2
NetFL1_1: FL1.1(Unbalance_Port) R32.2
NetFL1_3: FL1.3(Balance_Port) U10.2(RF_N)
NetFL1_4: FL1.4(Balance_Port) U10.1(RF_P)
NetR26_2: R26.2 U11.12(P2.3/CAP0.2)
NetR27_2: R27.2 U11.14(P2.5/UCA1RXD/UCA1SOMI/CAP1.2)
NetR29_2: R29.2 R30.2 R32.1
NetR34_2: R34.2 U13.7(VREF_B) U13.8(EN)
NetR39_1: R39.1 S3.2 U18.3(PB1)

Not connected (* = marked no-connect by the designer): J4 1 4 5(M1) 6(M2); J5 6 7 8; U10 20(DIO_14) 36(DIO_23) 37(DIO_24) 38(DIO_25) 39(DIO_26) 40(DIO_27) 41(DIO_28) 42(DIO_29) 43(DIO_30); U12 2(GND) 3(GND) 4(GND); U14 14(NC) 16(NC)

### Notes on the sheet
- Pin 13
- Pin 22
- Pin 45
- Pin 48
- Pin 44
- (near C69) DNP
- (near C28) Pin 44
- (near R29) DNP
- (near C37) DNP
- (near R59) DNP
- (near R61) DNP
- (near C44) DNP
- (near C45) DNP
- 24MHz XTAL
- 32kHz XTAL
- (near C50) DNP
- Antenna
- (near R62) DNP
- DNP
- (near U14) I2C Address
  = 0101000
- (near C70) DNP

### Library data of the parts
C28 C36 C47 C69 = GRM155R61A105KE15D: as C24 on sheet WirelessDMM_PWR
C29-C33 C35 C38 C46 C51 C52 = CL03A104KP3NNNC: CAP, CERM, 0.1 µF, 10 V, +/- 10%, X5R, 0201; Manufacturer: Samsung Electro-Mechanics; Polarized: N; CompType: Capacitor; Value: 0.1uF; U/M: EA; Cap_F: 0.0000001; Tolerance_%: 10; Value1: Unknown; Value2: 10V; TaMin_C: -55; TaMax_C: 85; AEC Category: Q200
C34 = C1005X5R1A475K050BC: as C56 on sheet WirelessDMM_PWR
C37 = GRM1555C1H390JA01D: CAP, CERM, 39 pF, 50 V, +/- 5%, C0G/NP0, 0402; Manufacturer: MuRata; Polarized: N; CompType: Capacitor; Value: 39pF; U/M: EA; Cap_F: 0.000000000039; Tolerance_%: 5; Value1: Unknown; VDC_V: 50; Value2: 50V; TaMin_C: -55; TaMax_C: 125; Cap_Case: 0402; AEC Category: Q200; SizeArea_mm2: 0.5; SizeAreaWB_mm2: 3; SizeX_mm: 1; SizeZ_mm: 0.6
C39 = C1005X5R0J105M050BB: CAP, CERM, 1 µF, 6.3 V, +/- 20%, X5R, 0402; Manufacturer: TDK; Polarized: N; CompType: Capacitor; Value: 1uF; U/M: EA; Cap_F: 0.000001; Tolerance_%: 20; ESR_ohm: 0.0079; Value1: 0.0079 ohm; VDC_V: 6.3; Value2: 6.3V; TaMin_C: -55; TaMax_C: 85; Cap_Case: 0402; AEC Category: Q200
C40 C41 = GCM0335C1E220JD03D: CAP, CERM, 22 pF, 25 V, +/- 5%, C0G/NP0, AEC-Q200 Grade 1, 0201; Manufacturer: MuRata; Polarized: N; CompType: Capacitor; Value: 22pF; U/M: EA; Cap_F: 0.000000000022; Tolerance_%: 5; Value1: Unknown; VDC_V: 25; Value2: 25V; TaMin_C: -55; TaMax_C: 125; Cap_Case: 0201; AEC Category: Q200; AEC Qualified: Y; AEC Grade: 1
C42-C45 = GRM0335C1H120JA01D: CAP, CERM, 12 pF, 50 V, +/- 5%, C0G/NP0, 0201; Manufacturer: MuRata; Polarized: N; CompType: Capacitor; Value: 12pF; U/M: EA; Cap_F: 0.000000000012; Tolerance_%: 5; Value1: Unknown; VDC_V: 50; Value2: 50V; TaMin_C: -55; TaMax_C: 125; AEC Category: Q200
C48 = GRM033R60J474KE90D: as C53 on sheet WirelessDMM_PWR
C49 C50 = GRM1555C1H390JA01D: CAP, CERM, 39 pF, 50 V, +/- 5%, C0G/NP0, 0402; Manufacturer: MuRata; Polarized: N; CompType: Capacitor; Value: 39pF; U/M: EA; Cap_F: 0.000000000039; Tolerance_%: 5; Value1: Unknown; VDC_V: 50; Value2: 50V; TaMin_C: -55; TaMax_C: 125; Cap_Case: 0402; AEC Category: Q200
C70 = CL05A225KQ5NNNC: CAP, CERM, 2.2 µF, 6.3 V, +/- 10%, X5R, 0402; Manufacturer: Samsung; Polarized: N; CompType: Capacitor; Value: 2.2uF; U/M: EA; Cap_F: 0.0000022; Tolerance_%: 10; Value1: Unknown; VDC_V: 6.3; Value2: 6.3V; TaMin_C: -55; TaMax_C: 85; Cap_Case: 0402; AEC Category: Q200
FL1 = LFB182G45BG5D920: Filter, BandPass, 2.45GHz, SMD; Manufacturer: MuRata; SymbolCreator: Altium
J3 = 20021121-00006C4LF: Header, 1.27 mm, 3x2, Au, SMT; Manufacturer: FCI; SymbolCreator: a0412235
J4 = HFW4R-1STE1LF: CONN FFC BOTTOM 4POS 1.00MM R/A; Manufacturer: Amphenol FCI; Flat Flex Type: FFC, FPC; Connector/Contact Type: Contacts, Bottom; Number of Positions: 4; Pitch: 0.039" (1.00mm); FFC, FCB Thickness: 0.30mm; Cable End Type: Straight or Tapered; VDC_V: 100V; Material Flammability Rating: UL94 V-0; Current Rating: 1A
J5 = 20021121-00010C4LF: Header, 1.27mm, 5x2, Gold, SMT; Manufacturer: FCI; SymbolCreator: a0412235; Pitch_mm: 1.27; Gender: Male; Shrouded: N; Row_Count: 2
L3 = BLM18HE152SN1D: Ferrite Bead, 1500 ohm @ 100 MHz, 0.5 A, 0603; Manufacturer: MuRata; Imax_A: 0.5; Value1: 0.5 ohm; Value2: 0.5A; ZTyp@100MHz_Ohm: 1500
R26 R27 = CRCW0201909RFKED: RES, 909, 1%, 0.05 W, 0201; Manufacturer: Vishay-Dale; CompType: Resistor; Value: 909; Value_Code: 909R; Tolerance_%: 1; Power_W: 0.05; Value2: 0.05W; VDC_V: 30; TempCo: 100 ppm/C; EIA_Code: E96; U/M: EA; AEC Category: Q200
R29 R30 R32 R56-R58 = MCR01MZPJ000: RES, 0, 5%, 0.063 W, 0402; Manufacturer: Rohm; CompType: Resistor; Value: 0; Value_Code: 0000; Tolerance_%: 5; Power_W: 0.063; Value2: 0.063W; VDC_V: 50; TempCo: 500 ppm/C; EIA_Code: E24; U/M: EA; AEC Category: Q200
R33 R35-R38 R59-R64 = RK73H1HTTC4702F: RES, 47.0 k, 1%, 0.05 W, AEC-Q200 Grade 0, 0201; Manufacturer: KOA Speer; CompType: Resistor; Value: 47.0k; Res_ohm: 47000; Value_Code: 47k0; Tolerance_%: 1; Power_W: 0.05; Value2: 0.05W; VDC_V: 25; TempCo: 200 ppm/C; U/M: EA; AEC Category: Q200; AEC Qualified: Y; AEC Grade: 0; SizeArea_mm2: 0.18; SizeAreaWB_mm2: 2.08; SizeX_mm: 0.6; SizeY_mm: 0.3; SizeZ_mm: 0.26
R34 = CRCW0402200KFKED: RES, 200 k, 1%, 0.063 W, 0402; Manufacturer: Vishay-Dale; CompType: Resistor; Value: 200k; Res_ohm: 200000; Tolerance_%: 1; Power_W: 0.063; Value2: 0.063W; VDC_V: 50; TempCo: 100 ppm/C; EIA_Code: E96; U/M: EA; AEC Category: Q200
R39 = CRCW0201100KFKED: RES, 100 k, 1%, 0.05 W, 0201; Manufacturer: Vishay-Dale; CompType: Resistor; Value: 100k; Res_ohm: 100000; Tolerance_%: 1; Power_W: 0.05; Value2: 0.05W; VDC_V: 30; TempCo: 100 ppm/C; EIA_Code: E96; U/M: EA; AEC Category: Q200
R40 = CRCW02011K00FKED: RES, 1.00 k, 1%, 0.05 W, 0201; Manufacturer: Vishay-Dale; CompType: Resistor; Value: 1.00k; Res_ohm: 1000; Value_Code: 1k00; Tolerance_%: 1; Power_W: 0.05; Value2: 0.05W; VDC_V: 30; TempCo: 100 ppm/C; EIA_Code: E96; U/M: EA; AEC Category: Q200
R65 = RK73H1HTTC4702F: RES, 47.0 k, 1%, 0.05 W, AEC-Q200 Grade 0, 0201; Manufacturer: KOA Speer; CompType: Resistor; Res_ohm: 47000; Value_Code: 47k0; Tolerance_%: 1; Power_W: 0.05; Value2: 0.05W; VDC_V: 25; TempCo: 200 ppm/C; U/M: EA; AEC Category: Q200; AEC Qualified: Y; AEC Grade: 0; SizeArea_mm2: 0.18; SizeAreaWB_mm2: 2.08; SizeX_mm: 0.6; SizeY_mm: 0.3; SizeZ_mm: 0.26
S3 = B3U-1000P: SWITCH TACTILE SPST-NO 0.05A 12V; Manufacturer: Omron Electronic Components; SymbolCreator: a0412235; VDC_V: 12; SwitchFunction: Off-Mom; PositionCount: 1; CurrentRating_mA: 50
TP7 TP8 = TP_H0.45P0.75: Manufacturer: Texas Instruments; CompType: Pad
U10 = CC2640F128RGZR: Ultra low-power ARM Cortex M3 2.4 GHz Radio MCU, Bluetooth Low Energy, RGZ0048A; Alternate PartNumber: CC2640F128RGZT; Manufacturer: Texas Instruments; SymbolCreator: a0412235; CompType: IC; U/M: EA
U11 = MSP430FR2532IRGER: Mixed-Signal Microcontrollers, RGE0024G; Alternate PartNumber: MSP430FR2532IRGET; Manufacturer: Texas Instruments; SymbolCreator: Altium; SizeX_mm: 4; SizeZ_mm: 1; CompType: IC; U/M: EA
U12 = 479480001: 2.4GHz Antenna, 50 Ohms, SMD; Manufacturer: Molex; SymbolCreator: Altium
U13 = LSF0102DQER: 2-Channel Bidirectional Multi-Voltage Level Translator for Open-Drain & Push-Pull Application, DQE0008A; Manufacturer: Texas Instruments; SymbolCreator: Altium; SizeX_mm: 1; SizeY_mm: 1.4; SizeZ_mm: 0.4; CompType: IC; U/M: EA
U14 = RF430CL330HIRGTR: DYNAMIC NFC INTERFACE TRANSPONDER, RGT0016C; Manufacturer: Texas Instruments; SymbolCreator: a0411947; CompType: IC; U/M: EA
U15 U16 = TPD1E10B06DPYR: ESD in 0402 Package with 10 pF Capacitance and 6 V Breakdown, 1 Channel, -40 to +125 degC, 2-pin X2SON (DPY), Green (RoHS & no Sb/Br); Manufacturer: Texas Instruments; Alternate PartNumber: Equivalent; Breakdown Voltage(Min)(V): 6; Eco-Plan: TBD; IEC 61000-4-2 Air-Gap(+/- kV): 30; IO Capacitance(Typ)(pF): 10; SubFamily: ESD Solution
U17 = LSF0204RUTR: 4-Bits Bidirectional Multi-Voltage Level Translator for Open-Drain and PushPull Application, RUT0012A; Manufacturer: Texas Instruments; SymbolCreator: Altium; SizeX_mm: 1.7; SizeY_mm: 2; SizeZ_mm: 0.55; CompType: IC; U/M: EA; SizeArea_mm2: 3.4; SizeAreaWB_mm2: 8.1
U18 = TPS3422EGDRYR: Low-Power, Push-Button Controllers With Configurable Delay, DRY0006A; Alternate PartNumber: TPS3422EGDRYT; Manufacturer: Texas Instruments; SymbolCreator: Altium; CompType: IC; U/M: EA
Y1 = FC-135 32.7680KA-A3: Crystal, 32.768 KHz, 12.5 pF, SMD; Manufacturer: Epson; SymbolCreator: a0412235; U/M: EA; TaMin_C: -40; TaMax_C: 85; Frequency Stability: ±20ppm
Y2 = FC-12M 32.7680KA-A3: Crystal, 32.768kHz, 12.5pF, SMD; Manufacturer: Epson; SymbolCreator: a0412235; U/M: EA; TaMin_C: -40; TaMax_C: 85; Frequency Stability: ±20ppm
Y3 = TSX-3225 24.0000MF20G-AC3: Crystal, 24 MHz, 9 pF, SMD; Manufacturer: Epson; SymbolCreator: a0412235; U/M: EA; TaMin_C: -40; TaMax_C: 85; Frequency Stability: ±20ppm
